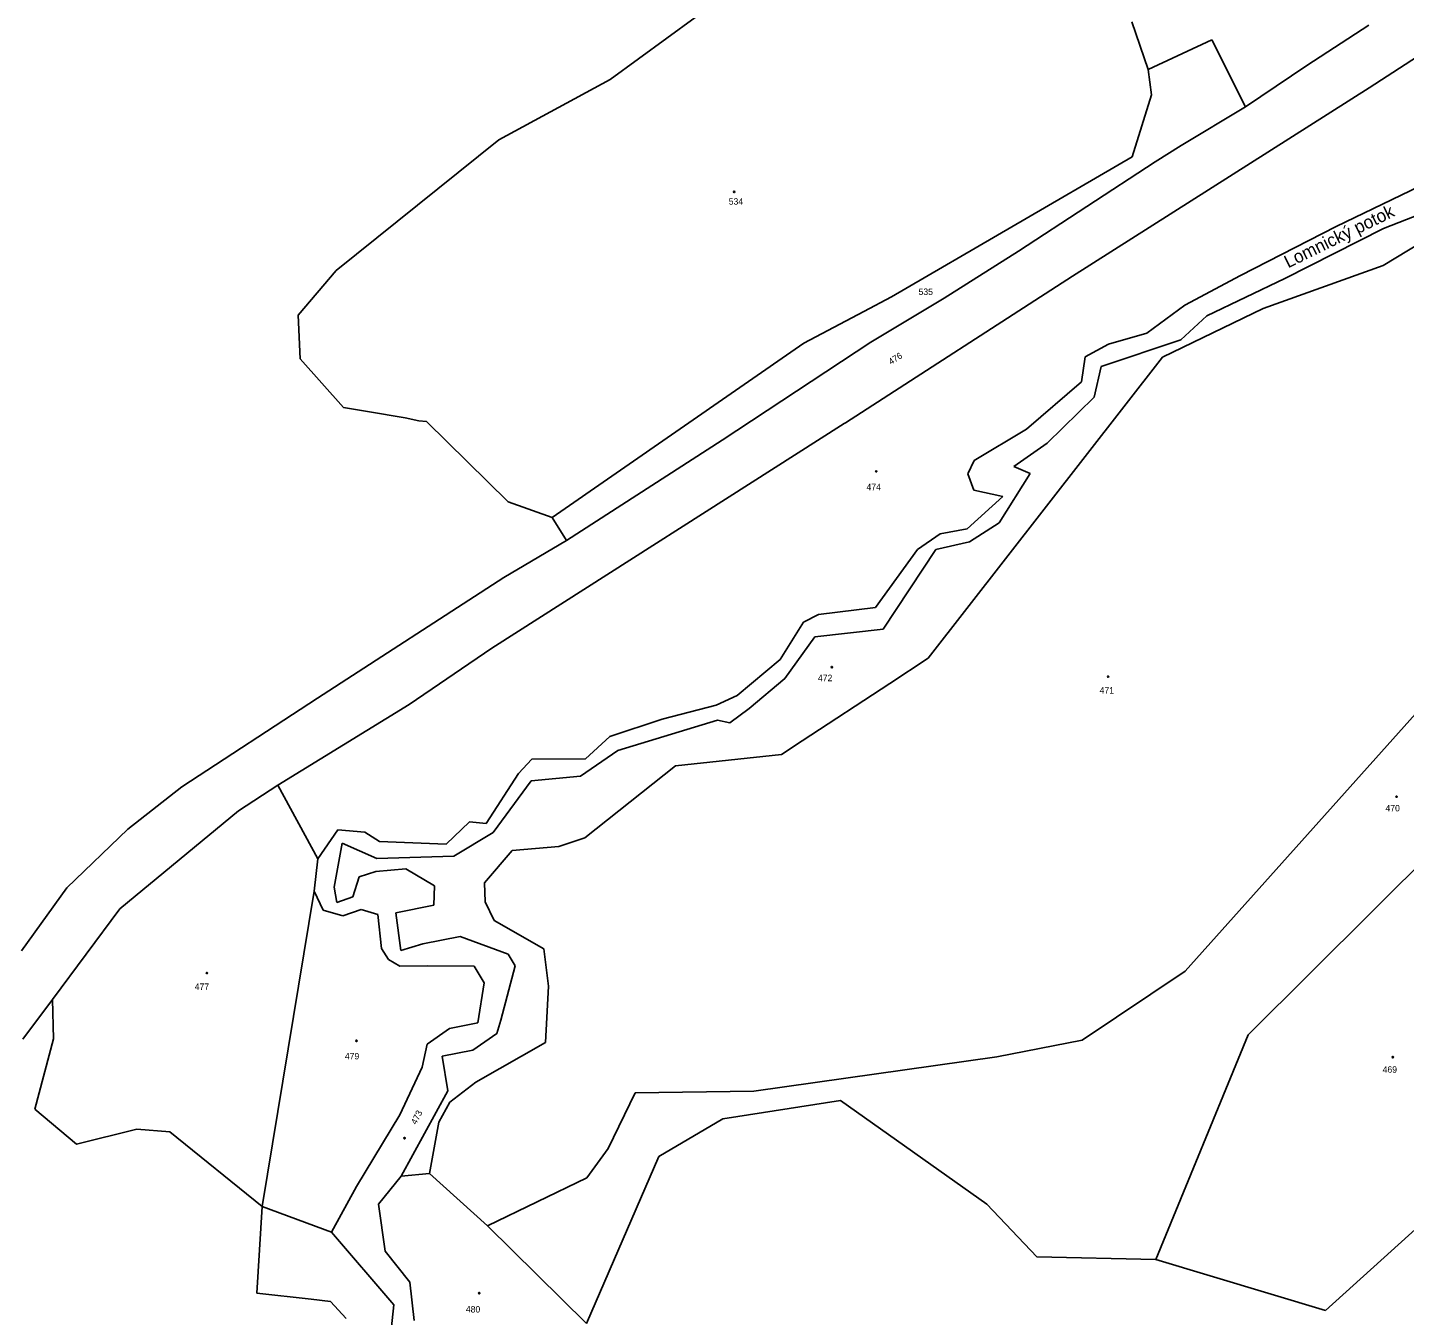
# Model space of a CAD drawing. Extents: x -841286 to -834997, y -1020681 to -1017810.
# Drawn here: x -840374 to -840011, y -1018654.1 to -1018314.4 of the extents above; entities that cross this region are included whole.
import ezdxf

# ---------------------------------------------------------------- set-up
doc = ezdxf.new("R2010")
doc.units = 0
for name, color, linetype in [('NERES_SET', 7, 'Continuous'), ('OVNE_POP', 7, 'Continuous'), ('OVNE_PRE', 7, 'Continuous'), ('OVNE_SET', 7, 'Continuous')]:
    doc.layers.add(name, color=color, linetype=linetype)

msp = doc.modelspace()

# ---------------------------------------------------------------- linework, layer by layer
at = {"layer": 'OVNE_POP'}
for points in [[(-840187.65, -1018357.58), (-840187.56, -1018357.73), (-840187.65, -1018357.88), (-840187.83, -1018357.88), (-840187.92, -1018357.73), (-840187.83, -1018357.58)], [(-840150.16, -1018431.34), (-840150.07, -1018431.49), (-840150.16, -1018431.64), (-840150.34, -1018431.64), (-840150.43, -1018431.49), (-840150.34, -1018431.34)], [(-840161.87, -1018482.99), (-840161.78, -1018483.14), (-840161.87, -1018483.29), (-840162.05, -1018483.29), (-840162.14, -1018483.14), (-840162.05, -1018482.99)], [(-840089.04, -1018485.47), (-840088.95, -1018485.62), (-840089.04, -1018485.77), (-840089.22, -1018485.77), (-840089.31, -1018485.62), (-840089.22, -1018485.47)], [(-840013, -1018517.13), (-840012.91, -1018517.28), (-840013, -1018517.43), (-840013.18, -1018517.43), (-840013.27, -1018517.28), (-840013.18, -1018517.13)], [(-840326.67, -1018563.64), (-840326.58, -1018563.79), (-840326.67, -1018563.94), (-840326.85, -1018563.94), (-840326.94, -1018563.79), (-840326.85, -1018563.64)], [(-840287.24, -1018581.53), (-840287.15, -1018581.68), (-840287.24, -1018581.83), (-840287.42, -1018581.83), (-840287.51, -1018581.68), (-840287.42, -1018581.53)], [(-840014.01, -1018585.86), (-840013.92, -1018586.01), (-840014.01, -1018586.16), (-840014.19, -1018586.16), (-840014.28, -1018586.01), (-840014.19, -1018585.86)], [(-840274.54, -1018607.52), (-840274.72, -1018607.53), (-840274.81, -1018607.39), (-840274.74, -1018607.22), (-840274.56, -1018607.21), (-840274.47, -1018607.35)], [(-840254.83, -1018648.13), (-840254.74, -1018648.28), (-840254.83, -1018648.43), (-840255.01, -1018648.43), (-840255.1, -1018648.28), (-840255.01, -1018648.13)]]:
    msp.add_lwpolyline(points, close=True, dxfattribs=at)
at = {"layer": 'OVNE_SET'}
for p, q in [((-840156.73, -1018281.58), (-840220.44, -1018328.08)), ((-840082.84, -1018312.91), (-840078.58, -1018325.44)), ((-840020.39, -1018313.75), (-840036.73, -1018324.37)), ((-840020.33, -1018330.28), (-839996.91, -1018315.06)), ((-840078.58, -1018325.44), (-840061.78, -1018317.65)), ((-840061.78, -1018317.65), (-840052.92, -1018335.27)), ((-840078.58, -1018325.44), (-840077.71, -1018332.14)), ((-840036.73, -1018324.37), (-840052.92, -1018335.27)), ((-840220.44, -1018328.08), (-840249.75, -1018344.02)), ((-840098.52, -1018379.96), (-840020.33, -1018330.28)), ((-840077.71, -1018332.14), (-840082.75, -1018348.47)), ((-840052.92, -1018335.27), (-840069.9, -1018345.51)), ((-840249.75, -1018344.02), (-840292.64, -1018378.52)), ((-840069.9, -1018345.51), (-840076.73, -1018349.84)), ((-840082.75, -1018348.47), (-840146.28, -1018385.45)), ((-840076.73, -1018349.84), (-840112.8, -1018373.42)), ((-840004.55, -1018355.08), (-840029.01, -1018366.84)), ((-840016.53, -1018367.39), (-839986.9, -1018355.83)), ((-840029.01, -1018366.84), (-840054.24, -1018379.81)), ((-840016.62, -1018377.18), (-839997.49, -1018365.52)), ((-840042.58, -1018380.6), (-840016.53, -1018367.39)), ((-840112.8, -1018373.42), (-840132.37, -1018385.8)), ((-840048.23, -1018388.54), (-840016.62, -1018377.18)), ((-840292.64, -1018378.52), (-840302.72, -1018390.24)), ((-840158.35, -1018418.65), (-840098.52, -1018379.96)), ((-840054.24, -1018379.81), (-840068.87, -1018387.64)), ((-840063.13, -1018390.46), (-840042.58, -1018380.6)), ((-840146.28, -1018385.45), (-840153.5, -1018389.28)), ((-840132.37, -1018385.8), (-840151.72, -1018397.42)), ((-840068.87, -1018387.64), (-840078.96, -1018395.01)), ((-840074.8, -1018401.31), (-840048.23, -1018388.54)), ((-840302.72, -1018390.24), (-840302.14, -1018401.76)), ((-840153.5, -1018389.28), (-840169.32, -1018397.68)), ((-840069.95, -1018396.75), (-840063.13, -1018390.46)), ((-840078.96, -1018395.01), (-840089.02, -1018397.92)), ((-840169.32, -1018397.68), (-840235.74, -1018443.6)), ((-840151.72, -1018397.42), (-840190.91, -1018423.27)), ((-840089.02, -1018397.92), (-840095.2, -1018401.24)), ((-840090.95, -1018403.78), (-840069.95, -1018396.75)), ((-840302.14, -1018401.76), (-840290.74, -1018414.63)), ((-840136.59, -1018480.77), (-840074.8, -1018401.31)), ((-840095.2, -1018401.24), (-840096.11, -1018407.87)), ((-840092.83, -1018411.88), (-840090.95, -1018403.78)), ((-840096.11, -1018407.87), (-840110.69, -1018420.34)), ((-840105.23, -1018424.04), (-840092.83, -1018411.88)), ((-840290.74, -1018414.63), (-840284.38, -1018415.67)), ((-840284.38, -1018415.67), (-840274.5, -1018417.34)), ((-840274.5, -1018417.34), (-840270.87, -1018418.1)), ((-840270.87, -1018418.1), (-840268.82, -1018418.29)), ((-840268.82, -1018418.29), (-840247.28, -1018439.48)), ((-840251.62, -1018478.09), (-840158.7, -1018418.87)), ((-840158.7, -1018418.87), (-840158.35, -1018418.65)), ((-840110.69, -1018420.34), (-840124.43, -1018428.63)), ((-840190.91, -1018423.27), (-840231.9, -1018449.67)), ((-840114.02, -1018430.17), (-840105.23, -1018424.04)), ((-840124.43, -1018428.63), (-840126.11, -1018432.13)), ((-840126.11, -1018432.13), (-840124.51, -1018436.41)), ((-840117.82, -1018445.01), (-840109.66, -1018432.06)), ((-840109.66, -1018432.06), (-840114.02, -1018430.17)), ((-840247.28, -1018439.48), (-840235.74, -1018443.6)), ((-840116.85, -1018438.09), (-840126.29, -1018446.59)), ((-840124.51, -1018436.41), (-840116.85, -1018438.09)), ((-840235.74, -1018443.6), (-840231.9, -1018449.67)), ((-840126.29, -1018446.59), (-840133.42, -1018447.94)), ((-840125.72, -1018450.08), (-840117.82, -1018445.01)), ((-840231.9, -1018449.67), (-840248.44, -1018459.43)), ((-840133.42, -1018447.94), (-840139.42, -1018452.06)), ((-840134.57, -1018452.12), (-840125.72, -1018450.08)), ((-840139.42, -1018452.06), (-840150.44, -1018467.41)), ((-840148.44, -1018473.14), (-840134.57, -1018452.12)), ((-840248.44, -1018459.43), (-840297.61, -1018491.31)), ((-839978.32, -1018462.11), (-840068.79, -1018563.35)), ((-840150.44, -1018467.41), (-840165.46, -1018469.27)), ((-840169.45, -1018471.25), (-840175.64, -1018481.12)), ((-840165.46, -1018469.27), (-840169.45, -1018471.25)), ((-840174.37, -1018486.15), (-840166.43, -1018475.1)), ((-840166.43, -1018475.1), (-840148.44, -1018473.14)), ((-840273.4, -1018493), (-840251.62, -1018478.09)), ((-840175.64, -1018481.12), (-840186.91, -1018490.56)), ((-840146.69, -1018487.4), (-840136.59, -1018480.77)), ((-840183.81, -1018494.06), (-840174.37, -1018486.15)), ((-840186.91, -1018490.56), (-840192.47, -1018493.12)), ((-840169.78, -1018502.58), (-840146.69, -1018487.4)), ((-840297.61, -1018491.31), (-840333.34, -1018514.7)), ((-840308.01, -1018514.22), (-840273.4, -1018493)), ((-840192.47, -1018493.12), (-840206.73, -1018496.8)), ((-840188.9, -1018497.81), (-840183.81, -1018494.06)), ((-840206.73, -1018496.8), (-840220.51, -1018501.45)), ((-840218.43, -1018505.12), (-840192.1, -1018497.14)), ((-840192.1, -1018497.14), (-840188.9, -1018497.81)), ((-840220.51, -1018501.45), (-840226.96, -1018507.28)), ((-840052.2, -1018580.15), (-839970.15, -1018498.35)), ((-840228.22, -1018511.91), (-840218.43, -1018505.12)), ((-840175.22, -1018506.15), (-840169.78, -1018502.58)), ((-840241.05, -1018507.38), (-840244.62, -1018511.17)), ((-840226.96, -1018507.28), (-840241.05, -1018507.38)), ((-840203.17, -1018509.15), (-840175.22, -1018506.15)), ((-840244.62, -1018511.17), (-840253.12, -1018524.39)), ((-840241.23, -1018513.1), (-840228.22, -1018511.91)), ((-840227.11, -1018528.13), (-840203.17, -1018509.15)), ((-840333.34, -1018514.7), (-840347.57, -1018525.86)), ((-840318.38, -1018520.99), (-840308.01, -1018514.22)), ((-840297.52, -1018533.73), (-840308.01, -1018514.22)), ((-840251.28, -1018526.76), (-840241.23, -1018513.1)), ((-840349.74, -1018546.85), (-840318.38, -1018520.99)), ((-840347.57, -1018525.86), (-840363.66, -1018541.36)), ((-840292.23, -1018526.03), (-840297.52, -1018533.73)), ((-840285.11, -1018526.63), (-840292.23, -1018526.03)), ((-840281.2, -1018529.15), (-840285.11, -1018526.63)), ((-840257.47, -1018523.94), (-840263.67, -1018529.85)), ((-840261.63, -1018533), (-840251.28, -1018526.76)), ((-840253.12, -1018524.39), (-840257.47, -1018523.94)), ((-840293.19, -1018541.12), (-840291.06, -1018529.54)), ((-840291.06, -1018529.54), (-840281.96, -1018533.6)), ((-840263.67, -1018529.85), (-840281.2, -1018529.15)), ((-840246.25, -1018531.53), (-840233.96, -1018530.47)), ((-840233.96, -1018530.47), (-840227.11, -1018528.13)), ((-840297.52, -1018533.73), (-840298.51, -1018542.25)), ((-840281.96, -1018533.6), (-840261.63, -1018533)), ((-840253.59, -1018540), (-840246.25, -1018531.53)), ((-840282.22, -1018537.01), (-840286.56, -1018538.47)), ((-840274.27, -1018536.35), (-840282.22, -1018537.01)), ((-840266.71, -1018540.83), (-840274.27, -1018536.35)), ((-840363.66, -1018541.36), (-840375.59, -1018557.99)), ((-840292.46, -1018545.18), (-840293.19, -1018541.12)), ((-840286.56, -1018538.47), (-840288.3, -1018543.72)), ((-840266.92, -1018545.92), (-840266.71, -1018540.83)), ((-840253.38, -1018545.03), (-840253.59, -1018540)), ((-840312.14, -1018625.38), (-840298.51, -1018542.25)), ((-840298.51, -1018542.25), (-840296.1, -1018547.2)), ((-840288.3, -1018543.72), (-840292.46, -1018545.18)), ((-840250.98, -1018549.98), (-840253.38, -1018545.03)), ((-840367.5, -1018570.75), (-840349.74, -1018546.85)), ((-840296.1, -1018547.2), (-840290.91, -1018548.75)), ((-840290.91, -1018548.75), (-840286.1, -1018547.07)), ((-840286.1, -1018547.07), (-840281.64, -1018548.36)), ((-840281.64, -1018548.36), (-840280.7, -1018557.35)), ((-840276.93, -1018547.96), (-840266.92, -1018545.92)), ((-840275.61, -1018557.86), (-840276.93, -1018547.96)), ((-840237.9, -1018557.46), (-840250.98, -1018549.98)), ((-840269.8, -1018556.14), (-840275.61, -1018557.86)), ((-840260, -1018554.17), (-840269.8, -1018556.14)), ((-840247.33, -1018558.81), (-840260, -1018554.17)), ((-840280.7, -1018557.35), (-840278.89, -1018560.2)), ((-840245.43, -1018561.95), (-840247.33, -1018558.81)), ((-840236.65, -1018567.29), (-840237.9, -1018557.46)), ((-840278.89, -1018560.2), (-840275.86, -1018561.96)), ((-840275.86, -1018561.96), (-840268.53, -1018561.91)), ((-840268.53, -1018561.91), (-840256.29, -1018561.96)), ((-840256.29, -1018561.96), (-840253.62, -1018566.44)), ((-840249.21, -1018576.24), (-840245.43, -1018561.95)), ((-840068.79, -1018563.35), (-840096.01, -1018581.49)), ((-840253.62, -1018566.44), (-840255.34, -1018576.97)), ((-840237.47, -1018582.17), (-840236.65, -1018567.29)), ((-840375.3, -1018581.26), (-840367.5, -1018570.75)), ((-840367.5, -1018570.75), (-840367.21, -1018581.13)), ((-840255.34, -1018576.97), (-840262.82, -1018578.47)), ((-840250.33, -1018579.73), (-840249.21, -1018576.24)), ((-840367.21, -1018581.13), (-840372.09, -1018599.74)), ((-840262.82, -1018578.47), (-840268.66, -1018582.58)), ((-840256.59, -1018584.15), (-840250.33, -1018579.73)), ((-840096.01, -1018581.49), (-840118.45, -1018585.88)), ((-840076.59, -1018639.39), (-840052.2, -1018580.15)), ((-840268.66, -1018582.58), (-840269.98, -1018588.66)), ((-840264.74, -1018585.73), (-840256.59, -1018584.15)), ((-840255.83, -1018592.62), (-840237.47, -1018582.17)), ((-840269.98, -1018588.66), (-840275.87, -1018601.25)), ((-840263.25, -1018594.92), (-840264.74, -1018585.73)), ((-840118.45, -1018585.88), (-840182.55, -1018594.99)), ((-840275.5, -1018617.38), (-840263.25, -1018594.92)), ((-840262.71, -1018597.9), (-840255.83, -1018592.62)), ((-840213.79, -1018595.38), (-840220.91, -1018610.1)), ((-840182.55, -1018594.99), (-840213.79, -1018595.38)), ((-840265.6, -1018603.13), (-840262.71, -1018597.9)), ((-840159.67, -1018597.46), (-840190.74, -1018602.24)), ((-840121.13, -1018624.76), (-840159.67, -1018597.46)), ((-840372.09, -1018599.74), (-840361.09, -1018609)), ((-840275.87, -1018601.25), (-840287.33, -1018620.15)), ((-840268.03, -1018616.7), (-840265.6, -1018603.13)), ((-840190.74, -1018602.24), (-840207.61, -1018612.19)), ((-840361.09, -1018609), (-840345.25, -1018605.01)), ((-840345.25, -1018605.01), (-840336.53, -1018605.71)), ((-840336.53, -1018605.71), (-840312.14, -1018625.38)), ((-840220.91, -1018610.1), (-840226.59, -1018617.87)), ((-840207.61, -1018612.19), (-840226.67, -1018656.26)), ((-840275.5, -1018617.38), (-840281.49, -1018624.75)), ((-840275.5, -1018617.38), (-840268.03, -1018616.7)), ((-840252.77, -1018630.47), (-840268.03, -1018616.7)), ((-840226.59, -1018617.87), (-840252.77, -1018630.47)), ((-840287.33, -1018620.15), (-840293.91, -1018632.16)), ((-840281.49, -1018624.75), (-840279.77, -1018637.17)), ((-840107.93, -1018638.7), (-840121.13, -1018624.76)), ((-840312.14, -1018625.38), (-840313.59, -1018648.22)), ((-840293.91, -1018632.16), (-840312.14, -1018625.38)), ((-840293.91, -1018632.16), (-840277.48, -1018651.3)), ((-840226.67, -1018656.26), (-840252.77, -1018630.47)), ((-840007.23, -1018630.56), (-840031.8, -1018652.87)), ((-840279.77, -1018637.17), (-840273.28, -1018645.36)), ((-840076.59, -1018639.39), (-840107.93, -1018638.7)), ((-840031.8, -1018652.87), (-840076.59, -1018639.39)), ((-840273.28, -1018645.36), (-840272.09, -1018655.48)), ((-840313.59, -1018648.22), (-840299.27, -1018649.88)), ((-840299.27, -1018649.88), (-840294.16, -1018650.48)), ((-840294.16, -1018650.48), (-840290.06, -1018654.91)), ((-840277.48, -1018651.3), (-840278.42, -1018660.39))]:
    msp.add_line(p, q, dxfattribs=at)

# ---------------------------------------------------------------- texts
at = {"layer": 'NERES_SET'}
msp.add_text('Lomnický potok', height=3.4, rotation=26.1269, dxfattribs=at).set_placement((-840041.67, -1018377.94))
at = {"layer": 'OVNE_PRE'}
for s, p in [('534', (-840189.16, -1018361.12)), ('535', (-840139.11, -1018384.94)), ('474', (-840152.84, -1018436.44)), ('472', (-840165.64, -1018486.82)), ('471', (-840091.37, -1018490.09)), ('470', (-840016, -1018521.17)), ('477', (-840329.96, -1018568.27)), ('479', (-840290.37, -1018586.6)), ('469', (-840016.75, -1018590.12)), ('480', (-840258.47, -1018653.36))]:
    msp.add_text(s, height=1.7, dxfattribs=at).set_placement(p)
for s, rotation, p in [('476', 32.1429, (-840146.41, -1018403.44)), ('473', 63.1972, (-840271.56, -1018603.95))]:
    msp.add_text(s, height=1.7, rotation=rotation, dxfattribs=at).set_placement(p)

doc.saveas('drawing.dxf')
